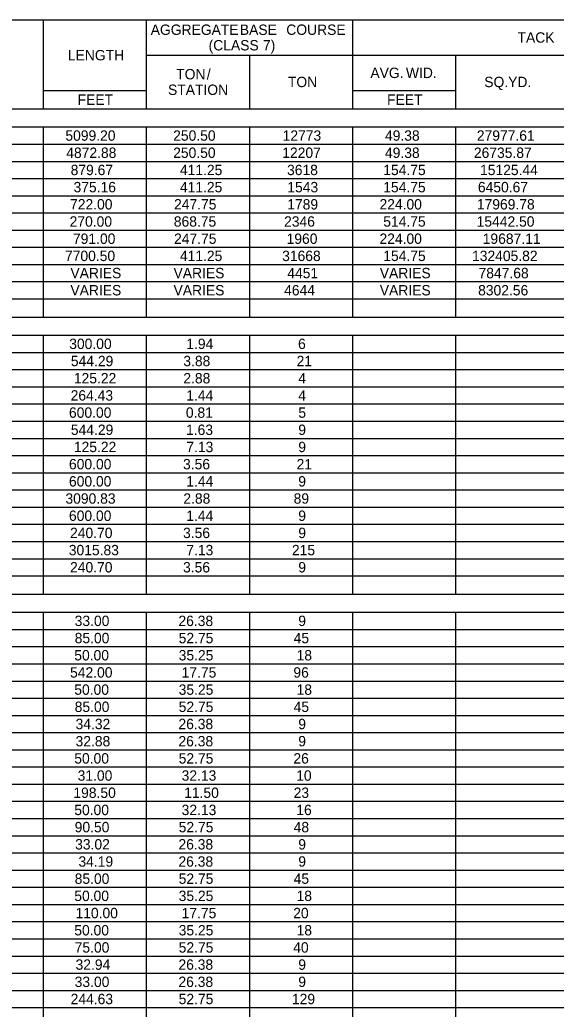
# Model space of a CAD drawing. Extents: x 1226590 to 1228573, y 151304 to 154224.
# Drawn here: x 1226850.3 to 1227053.8, y 151806.5 to 152182 of the extents above; entities that cross this region are included whole.
import ezdxf

# ---------------------------------------------------------------- set-up
doc = ezdxf.new("R2010")
doc.units = 0
doc.layers.add('R_Dimension', color=7, linetype='Continuous')

msp = doc.modelspace()

# ---------------------------------------------------------------- linework, layer by layer
at = {"layer": 'R_Dimension'}
for p, q in [((1226590.27, 152182.03), (1228150.73, 152182.03)), ((1226859.24, 152148.27), (1226859.24, 152182.03)), ((1226898.37, 152148.27), (1226898.37, 152182.03)), ((1226976.64, 152148.27), (1226976.64, 152182.03)), ((1226898.37, 152168.6), (1228150.73, 152168.6)), ((1226937.51, 152148.27), (1226937.51, 152168.6)), ((1227015.78, 152148.27), (1227015.78, 152168.6)), ((1226859.24, 152155.17), (1226898.37, 152155.17)), ((1226976.64, 152155.17), (1227015.78, 152155.17)), ((1226590.27, 152148.27), (1228150.73, 152148.27)), ((1226898.37, 152148.27), (1227015.78, 152148.27)), ((1227015.78, 152148.27), (1227172.32, 152148.27)), ((1226590.27, 152141.36), (1228150.73, 152141.36)), ((1226859.24, 152069.23), (1226859.24, 152141.36)), ((1226898.37, 152069.23), (1226898.37, 152141.36)), ((1226937.51, 152069.23), (1226937.51, 152141.36)), ((1226976.64, 152069.23), (1226976.64, 152141.36)), ((1227015.78, 152069.23), (1227015.78, 152141.36)), ((1226590.27, 152134.84), (1228150.73, 152134.84)), ((1226590.27, 152128.31), (1228150.73, 152128.31)), ((1226590.27, 152121.79), (1228150.73, 152121.79)), ((1226590.27, 152115.27), (1228150.73, 152115.27)), ((1226590.27, 152108.75), (1228150.73, 152108.75)), ((1226590.27, 152102.22), (1228150.73, 152102.22)), ((1226590.27, 152095.7), (1228150.73, 152095.7)), ((1226590.27, 152089.18), (1228150.73, 152089.18)), ((1226590.27, 152082.65), (1228150.73, 152082.65)), ((1226590.27, 152076.13), (1228150.73, 152076.13)), ((1226590.27, 152069.23), (1228150.73, 152069.23)), ((1226590.27, 152062.32), (1228150.73, 152062.32)), ((1226859.24, 151964.1), (1226859.24, 152062.32)), ((1226898.37, 151964.1), (1226898.37, 152062.32)), ((1226937.51, 151964.1), (1226937.51, 152062.32)), ((1226976.64, 151964.1), (1226976.64, 152062.32)), ((1227015.78, 151964.1), (1227015.78, 152062.32)), ((1226590.27, 152055.8), (1228150.73, 152055.8)), ((1226590.27, 152049.27), (1228150.73, 152049.27)), ((1226590.27, 152042.75), (1228150.73, 152042.75)), ((1226590.27, 152036.23), (1228150.73, 152036.23)), ((1226590.27, 152029.71), (1228150.73, 152029.71)), ((1226590.27, 152023.18), (1228150.73, 152023.18)), ((1226590.27, 152016.66), (1228150.73, 152016.66)), ((1226590.27, 152010.14), (1228150.73, 152010.14)), ((1226590.27, 152003.61), (1228150.73, 152003.61)), ((1226590.27, 151997.09), (1228150.73, 151997.09)), ((1226590.27, 151990.57), (1228150.73, 151990.57)), ((1226590.27, 151984.05), (1228150.73, 151984.05)), ((1226590.27, 151977.52), (1228150.73, 151977.52)), ((1226590.27, 151971), (1228150.73, 151971)), ((1226590.27, 151964.1), (1228150.73, 151964.1)), ((1226590.27, 151957.19), (1228150.73, 151957.19)), ((1226859.24, 151500.6), (1226859.24, 151957.19)), ((1226898.37, 151500.6), (1226898.37, 151957.19)), ((1226937.51, 151484.92), (1226937.51, 151957.19)), ((1226976.64, 151484.92), (1226976.64, 151957.19)), ((1227015.78, 151484.92), (1227015.78, 151957.19)), ((1226590.27, 151950.67), (1228150.73, 151950.67)), ((1226590.27, 151944.14), (1228150.73, 151944.14)), ((1226590.27, 151937.62), (1228150.73, 151937.62)), ((1226590.27, 151931.1), (1228150.73, 151931.1)), ((1226590.27, 151924.58), (1228150.73, 151924.58)), ((1226590.27, 151918.05), (1228150.73, 151918.05)), ((1226590.27, 151911.53), (1228150.73, 151911.53)), ((1226590.27, 151905.01), (1228150.73, 151905.01)), ((1226590.27, 151898.48), (1228150.73, 151898.48)), ((1226590.27, 151891.96), (1228150.73, 151891.96)), ((1226590.27, 151885.44), (1228150.73, 151885.44)), ((1226590.27, 151878.92), (1228150.73, 151878.92)), ((1226590.27, 151872.39), (1228150.73, 151872.39)), ((1226590.27, 151865.87), (1228150.73, 151865.87)), ((1226590.27, 151859.35), (1228150.73, 151859.35)), ((1226590.27, 151852.83), (1228150.73, 151852.83)), ((1226590.27, 151846.3), (1228150.73, 151846.3)), ((1226590.27, 151839.78), (1228150.73, 151839.78)), ((1226590.27, 151833.26), (1228150.73, 151833.26)), ((1226590.27, 151826.73), (1228150.73, 151826.73)), ((1226590.27, 151820.21), (1228150.73, 151820.21)), ((1226590.27, 151813.69), (1228150.73, 151813.69)), ((1226590.27, 151807.17), (1228150.73, 151807.17))]:
    msp.add_line(p, q, dxfattribs=at)

# ---------------------------------------------------------------- texts
for s, height, p in [('AGGREGATE', 3.935, (1226899.95, 152176.3)), (' BASE', 3.935, (1226932.3, 152176.3)), (' COURSE', 3.935, (1226949.93, 152176.3)), ('TACK', 3.935, (1227039.14, 152173.35)), ('(CLASS', 3.935, (1226921.92, 152170.4)), (' 7)', 3.935, (1226941.07, 152170.4)), ('LENGTH', 3.935, (1226868.52, 152166.63)), (' /', 3.935, (1226919.75, 152159.42)), ('AVG.', 3.935, (1226983.31, 152159.92)), (' WID.', 3.935, (1226995.33, 152159.92)), ('TON', 3.935, (1226909.62, 152159.42)), ('TON', 3.935, (1226952.01, 152156.47)), ('SQ.YD.', 3.935, (1227026.52, 152156.47)), ('STATION', 3.935, (1226906.52, 152153.51)), ('FEET', 3.935, (1226872.22, 152149.75)), ('FEET', 3.935, (1226989.63, 152149.75)), ('5099.20', 3.935, (1226867.57, 152136.13)), ('250.50', 3.935, (1226908.47, 152136.13)), ('12773', 3.935, (1226950.01, 152136.13)), ('49.38', 3.935, (1226988.84, 152136.13)), ('27977.61', 3.935, (1227023.7, 152136.13)), ('4872.88', 3.935, (1226867.9, 152129.61)), ('250.50', 3.935, (1226908.47, 152129.61)), ('12207', 3.935, (1226949.86, 152129.61)), ('49.38', 3.935, (1226988.84, 152129.61)), ('26735.87', 3.935, (1227022.58, 152129.61)), ('879.67', 3.935, (1226869.57, 152123.08)), ('411.25', 3.935, (1226911.03, 152123.08)), ('3618', 3.935, (1226951.68, 152123.08)), ('154.75', 3.935, (1226988.19, 152123.08)), ('15125.44', 3.935, (1227024.91, 152123.08)), ('375.16', 3.935, (1226870.67, 152116.56)), ('411.25', 3.935, (1226911.03, 152116.56)), ('1543', 3.935, (1226951.78, 152116.56)), ('154.75', 3.935, (1226988.19, 152116.56)), ('6450.67', 3.935, (1227024.1, 152116.56)), ('722.00', 3.935, (1226869.34, 152110.04)), ('247.75', 3.935, (1226908.8, 152110.04)), ('1789', 3.935, (1226951.76, 152110.04)), ('224.00', 3.935, (1226986.75, 152110.04)), ('17969.78', 3.935, (1227023.7, 152110.04)), ('270.00', 3.935, (1226869.18, 152103.52)), ('868.75', 3.935, (1226908.71, 152103.52)), ('2346', 3.935, (1226950.55, 152103.52)), ('514.75', 3.935, (1226988.19, 152103.52)), ('15442.50', 3.935, (1227023.62, 152103.52)), ('791.00', 3.935, (1226870.45, 152096.99)), ('247.75', 3.935, (1226908.8, 152096.99)), ('1960', 3.935, (1226951.51, 152096.99)), ('224.00', 3.935, (1226986.75, 152096.99)), ('19687.11', 3.935, (1227025.93, 152096.99)), ('7700.50', 3.935, (1226867.42, 152090.47)), ('411.25', 3.935, (1226911.03, 152090.47)), ('31668', 3.935, (1226949.82, 152090.47)), ('154.75', 3.935, (1226988.19, 152090.47)), ('132405.82', 3.935, (1227021.87, 152090.47)), ('VARIES', 3.935, (1226869.48, 152083.95)), ('VARIES', 3.935, (1226908.61, 152083.95)), ('4451', 3.935, (1226951.78, 152083.95)), ('VARIES', 3.935, (1226986.88, 152083.95)), ('7847.68', 3.935, (1227024.35, 152083.95)), ('VARIES', 3.935, (1226869.48, 152077.43)), ('VARIES', 3.935, (1226908.61, 152077.43)), ('4644', 3.935, (1226950.57, 152077.43)), ('VARIES', 3.935, (1226986.88, 152077.43)), ('8302.56', 3.935, (1227024.18, 152077.43)), ('300.00', 3.935, (1226869.03, 152057.09)), ('1.94', 3.935, (1226913.45, 152057.09)), ('6', 3.94, (1226955.85, 152057.09)), ('544.29', 3.935, (1226869.65, 152050.57)), ('3.88', 3.935, (1226912.33, 152050.57)), ('21', 3.935, (1226955.31, 152050.57)), ('125.22', 3.935, (1226870.78, 152044.04)), ('2.88', 3.935, (1226912.33, 152044.04)), ('4', 3.94, (1226955.96, 152044.04)), ('264.43', 3.935, (1226869.57, 152037.52)), ('1.44', 3.935, (1226913.45, 152037.52)), ('4', 3.94, (1226955.96, 152037.52)), ('600.00', 3.935, (1226868.93, 152031)), ('0.81', 3.935, (1226913.29, 152031)), ('5', 3.94, (1226955.96, 152031)), ('544.29', 3.935, (1226869.65, 152024.48)), ('1.63', 3.935, (1226913.35, 152024.48)), ('9', 3.94, (1226955.94, 152024.48)), ('125.22', 3.935, (1226870.78, 152017.95)), ('7.13', 3.935, (1226913.45, 152017.95)), ('9', 3.94, (1226955.94, 152017.95)), ('600.00', 3.935, (1226868.93, 152011.43)), ('3.56', 3.935, (1226912.22, 152011.43)), ('21', 3.935, (1226955.31, 152011.43)), ('600.00', 3.935, (1226868.93, 152004.91)), ('1.44', 3.935, (1226913.45, 152004.91)), ('9', 3.94, (1226955.94, 152004.91)), ('3090.83', 3.935, (1226867.59, 151998.39)), ('2.88', 3.935, (1226912.33, 151998.39)), ('89', 3.935, (1226954.18, 151998.39)), ('600.00', 3.935, (1226868.93, 151991.86)), ('1.44', 3.935, (1226913.45, 151991.86)), ('9', 3.94, (1226955.94, 151991.86)), ('240.70', 3.935, (1226869.34, 151985.34)), ('3.56', 3.935, (1226912.22, 151985.34)), ('9', 3.94, (1226955.94, 151985.34)), ('3015.83', 3.935, (1226868.86, 151978.82)), ('7.13', 3.935, (1226913.45, 151978.82)), ('215', 3.935, (1226953.54, 151978.82)), ('240.70', 3.935, (1226869.34, 151972.3)), ('3.56', 3.935, (1226912.22, 151972.3)), ('9', 3.94, (1226955.94, 151972.3)), ('33.00', 3.935, (1226871.1, 151951.96)), ('26.38', 3.935, (1226910.47, 151951.96)), ('9', 3.94, (1226955.94, 151951.96)), ('85.00', 3.935, (1226871.1, 151945.44)), ('52.75', 3.935, (1226910.56, 151945.44)), ('45', 3.935, (1226954.19, 151945.44)), ('50.00', 3.935, (1226870.95, 151938.91)), ('35.25', 3.935, (1226910.56, 151938.91)), ('18', 3.935, (1226955.31, 151938.91)), ('542.00', 3.935, (1226869.34, 151932.39)), ('17.75', 3.935, (1226911.68, 151932.39)), ('96', 3.935, (1226954.09, 151932.39)), ('50.00', 3.935, (1226870.95, 151925.87)), ('35.25', 3.935, (1226910.56, 151925.87)), ('18', 3.935, (1226955.31, 151925.87)), ('85.00', 3.935, (1226871.1, 151919.35)), ('52.75', 3.935, (1226910.56, 151919.35)), ('45', 3.935, (1226954.19, 151919.35)), ('34.32', 3.935, (1226871.43, 151912.82)), ('26.38', 3.935, (1226910.47, 151912.82)), ('9', 3.94, (1226955.94, 151912.82)), ('32.88', 3.935, (1226871.43, 151906.3)), ('26.38', 3.935, (1226910.47, 151906.3)), ('9', 3.94, (1226955.94, 151906.3)), ('50.00', 3.935, (1226870.95, 151899.78)), ('52.75', 3.935, (1226910.56, 151899.78)), ('26', 3.935, (1226954.09, 151899.78)), ('31.00', 3.935, (1226872.22, 151893.26)), ('32.13', 3.935, (1226911.68, 151893.26)), ('10', 3.935, (1226955.14, 151893.26)), ('198.50', 3.935, (1226870.61, 151886.73)), ('11.50', 3.935, (1226912.63, 151886.73)), ('23', 3.935, (1226954.19, 151886.73)), ('50.00', 3.935, (1226870.95, 151880.21)), ('32.13', 3.935, (1226911.68, 151880.21)), ('16', 3.935, (1226955.2, 151880.21)), ('90.50', 3.935, (1226871.1, 151873.69)), ('52.75', 3.935, (1226910.56, 151873.69)), ('48', 3.935, (1226954.19, 151873.69)), ('33.02', 3.935, (1226871.27, 151867.16)), ('26.38', 3.935, (1226910.47, 151867.16)), ('9', 3.94, (1226955.94, 151867.16)), ('34.19', 3.935, (1226872.53, 151860.64)), ('26.38', 3.935, (1226910.47, 151860.64)), ('9', 3.94, (1226955.94, 151860.64)), ('85.00', 3.935, (1226871.1, 151854.12)), ('52.75', 3.935, (1226910.56, 151854.12)), ('45', 3.935, (1226954.19, 151854.12)), ('50.00', 3.935, (1226870.95, 151847.6)), ('35.25', 3.935, (1226910.56, 151847.6)), ('18', 3.935, (1226955.31, 151847.6)), ('110.00', 3.935, (1226871.41, 151841.07)), ('17.75', 3.935, (1226911.68, 151841.07)), ('20', 3.935, (1226954.02, 151841.07)), ('50.00', 3.935, (1226870.95, 151834.55)), ('35.25', 3.935, (1226910.56, 151834.55)), ('18', 3.935, (1226955.31, 151834.55)), ('75.00', 3.935, (1226871.1, 151828.03)), ('52.75', 3.935, (1226910.56, 151828.03)), ('40', 3.935, (1226954.02, 151828.03)), ('32.94', 3.935, (1226871.43, 151821.51)), ('26.38', 3.935, (1226910.47, 151821.51)), ('9', 3.94, (1226955.94, 151821.51)), ('33.00', 3.935, (1226871.1, 151814.98)), ('26.38', 3.935, (1226910.47, 151814.98)), ('9', 3.94, (1226955.94, 151814.98)), ('244.63', 3.935, (1226869.57, 151808.46)), ('52.75', 3.935, (1226910.56, 151808.46)), ('129', 3.935, (1226953.53, 151808.46))]:
    msp.add_text(s, height=height, dxfattribs=at).set_placement(p)

doc.saveas('drawing.dxf')
